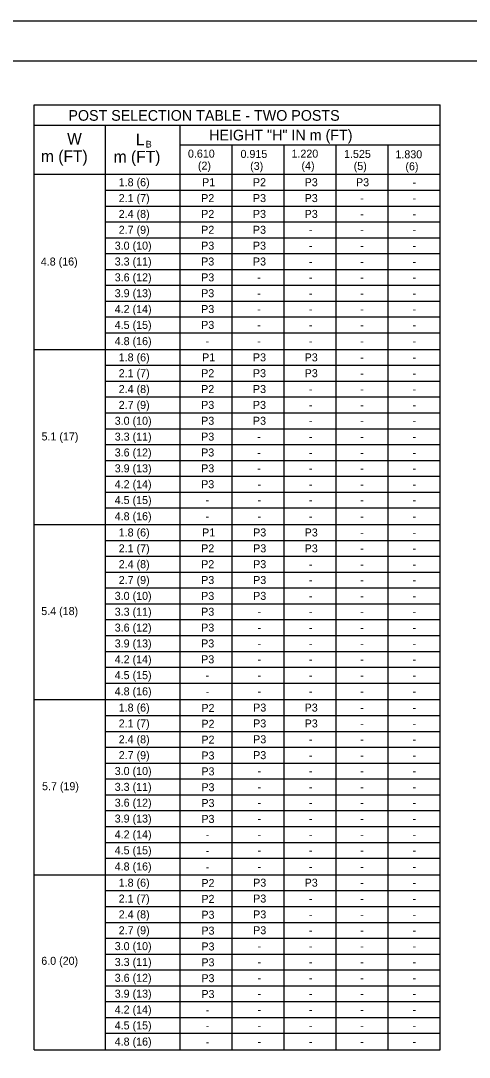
# Model space of a CAD drawing. Extents: x -1958 to 628, y -879 to 309.
# Drawn here: x -747.7 to -579.5, y -78.9 to 309.4 of the extents above; entities that cross this region are included whole.
import ezdxf

# ---------------------------------------------------------------- set-up
doc = ezdxf.new("R2010")
doc.units = 0
for name, color, linetype in [('1', 7, 'Continuous'), ('2', 7, 'Continuous'), ('PLT-BNDY', 7, 'Continuous')]:
    doc.layers.add(name, color=color, linetype=linetype)

msp = doc.modelspace()

# ---------------------------------------------------------------- linework, layer by layer
at = {"layer": '1'}
for p, q in [((-1077.39, 294.44), (-291.39, 294.44)), ((-742.69, 251.9), (-742.69, 277.92)), ((-742.69, 277.92), (-590.35, 277.92)), ((-590.35, 251.9), (-590.35, 277.92)), ((-742.69, 270.25), (-590.35, 270.25)), ((-715.89, -76.15), (-715.89, 270.25)), ((-687.88, -76.15), (-687.88, 270.25)), ((-668.38, -76.15), (-668.38, 262.9)), ((-648.87, -76.15), (-648.87, 262.9)), ((-629.36, -76.15), (-629.36, 262.9)), ((-609.85, -76.15), (-609.85, 262.9)), ((-742.69, -76.15), (-742.69, 251.9)), ((-742.69, 251.9), (-590.35, 251.9)), ((-649.54, 251.9), (-613.9, 251.9)), ((-613.9, 251.9), (-590.35, 251.9)), ((-590.35, -76.15), (-590.35, 251.9)), ((-715.89, 245.96), (-590.35, 245.96)), ((-715.89, 240.02), (-590.35, 240.02)), ((-649.54, 240.02), (-613.9, 240.02)), ((-613.9, 240.02), (-590.35, 240.02)), ((-715.89, 234.08), (-590.35, 234.08)), ((-715.89, 228.14), (-590.35, 228.14)), ((-715.89, 222.2), (-590.35, 222.2)), ((-715.89, 216.26), (-590.35, 216.26)), ((-715.89, 210.32), (-590.35, 210.32)), ((-715.89, 204.38), (-590.35, 204.38)), ((-715.89, 198.44), (-590.35, 198.44)), ((-715.89, 192.5), (-590.35, 192.5)), ((-742.69, 186.29), (-590.35, 186.29)), ((-715.89, 180.35), (-590.35, 180.35)), ((-715.89, 174.41), (-590.35, 174.41)), ((-715.89, 168.47), (-590.35, 168.47)), ((-715.89, 162.53), (-590.35, 162.53)), ((-715.89, 156.59), (-590.35, 156.59)), ((-715.89, 150.65), (-590.35, 150.65)), ((-715.89, 144.71), (-590.35, 144.71)), ((-715.89, 138.77), (-590.35, 138.77)), ((-715.89, 132.83), (-590.35, 132.83)), ((-715.89, 126.89), (-590.35, 126.89)), ((-742.69, 120.68), (-590.35, 120.68)), ((-715.89, 114.74), (-590.35, 114.74)), ((-715.89, 108.8), (-590.35, 108.8)), ((-715.89, 102.86), (-590.35, 102.86)), ((-715.89, 96.92), (-590.35, 96.92)), ((-715.89, 90.98), (-590.35, 90.98)), ((-715.89, 85.04), (-590.35, 85.04)), ((-715.89, 79.1), (-590.35, 79.1)), ((-715.89, 73.16), (-590.35, 73.16)), ((-715.89, 67.22), (-590.35, 67.22)), ((-715.89, 61.28), (-590.35, 61.28)), ((-742.69, 55.07), (-590.35, 55.07)), ((-715.89, 49.13), (-590.35, 49.13)), ((-715.89, 43.19), (-590.35, 43.19)), ((-715.89, 37.25), (-590.35, 37.25)), ((-715.89, 31.31), (-590.35, 31.31)), ((-715.89, 25.37), (-590.35, 25.37)), ((-715.89, 19.43), (-590.35, 19.43)), ((-715.89, 13.49), (-590.35, 13.49)), ((-715.89, 7.55), (-590.35, 7.55)), ((-715.89, 1.61), (-590.35, 1.61)), ((-715.89, -4.33), (-590.35, -4.33)), ((-742.69, -10.54), (-590.35, -10.54)), ((-613.9, -10.54), (-590.35, -10.54)), ((-715.89, -16.48), (-590.35, -16.48)), ((-613.9, -16.48), (-590.35, -16.48)), ((-715.89, -22.42), (-590.35, -22.42)), ((-613.9, -22.42), (-590.35, -22.42)), ((-715.89, -28.36), (-590.35, -28.36)), ((-613.9, -28.36), (-590.35, -28.36)), ((-715.89, -34.3), (-590.35, -34.3)), ((-715.89, -40.24), (-590.35, -40.24)), ((-613.9, -40.24), (-590.35, -40.24)), ((-715.89, -46.18), (-590.35, -46.18)), ((-613.9, -46.18), (-590.35, -46.18)), ((-715.89, -52.12), (-590.35, -52.12)), ((-613.9, -52.12), (-590.35, -52.12)), ((-715.89, -58.06), (-590.35, -58.06)), ((-613.9, -58.06), (-590.35, -58.06)), ((-715.89, -64), (-590.35, -64)), ((-613.9, -64), (-590.35, -64)), ((-715.89, -69.94), (-590.35, -69.94)), ((-613.9, -69.94), (-590.35, -69.94)), ((-742.69, -76.15), (-590.35, -76.15))]:
    msp.add_line(p, q, dxfattribs=at)
at = {"layer": '2'}
msp.add_line((-687.88, 262.9), (-590.35, 262.9), dxfattribs=at)
at = {"layer": 'PLT-BNDY'}
msp.add_lwpolyline([(-1117.39, 309.44), (-276.39, 309.44), (-276.39, -284.56), (-1117.39, -284.56)], close=True, dxfattribs=at)

# ---------------------------------------------------------------- texts
at = {"layer": '1'}
for s, height, p in [('POST SELECTION TABLE - TWO POSTS', 4.003, (-729.8, 271.96)), ('HEIGHT "H" IN m (FT)', 4.003, (-677.02, 264.6)), ('W', 4.37, (-730.29, 263.05)), ('L', 4.3, (-704.5, 262.77)), ('B', 2.5, (-700.8, 261.94)), ('m (FT)', 4.375, (-740.11, 256.48)), ('m (FT)', 4.375, (-712.84, 256.31)), ('0.610', 3, (-684.98, 258.14)), ('0.915', 3, (-665.26, 258.03)), ('1.220', 3, (-646.15, 258.14)), ('1.525', 3, (-626.43, 258.03)), ('1.830', 3, (-607.17, 257.9)), ('(2)', 3, (-681.24, 253.64)), ('(3)', 3, (-661.65, 253.53)), ('(4)', 3, (-642.4, 253.64)), ('(5)', 3, (-622.81, 253.53)), ('(6)', 3, (-603.42, 253.4)), ('1.8 (6)', 3, (-710.94, 247.43)), ('P1', 3, (-679.68, 247.43)), ('P2', 3, (-660.6, 247.43)), ('P3', 3, (-641.21, 247.43)), ('P3', 3, (-621.95, 247.43)), ('-', 3, (-600.73, 247.43)), ('2.1 (7)', 3, (-710.94, 241.49)), ('P2', 3, (-680.02, 241.49)), ('P3', 3, (-660.6, 241.49)), ('P3', 3, (-641.21, 241.49)), ('-', 3, (-620.33, 241.49)), ('-', 3, (-600.73, 241.49)), ('2.4 (8)', 3, (-710.94, 235.55)), ('P2', 3, (-680.02, 235.55)), ('P3', 3, (-660.6, 235.55)), ('P3', 3, (-641.21, 235.55)), ('-', 3, (-620.33, 235.55)), ('-', 3, (-600.73, 235.55)), ('2.7 (9)', 3, (-710.94, 229.61)), ('P2', 3, (-680.02, 229.61)), ('P3', 3, (-660.6, 229.61)), ('-', 3, (-639.59, 229.61)), ('-', 3, (-620.33, 229.61)), ('-', 3, (-600.73, 229.61)), ('3.0 (10)', 3, (-712.44, 223.67)), ('P3', 3, (-680.02, 223.67)), ('P3', 3, (-660.6, 223.67)), ('-', 3, (-639.59, 223.67)), ('-', 3, (-620.33, 223.67)), ('-', 3, (-600.73, 223.67)), ('4.8 (16)', 3, (-740.16, 217.71)), ('3.3 (11)', 3, (-712.44, 217.73)), ('P3', 3, (-680.02, 217.73)), ('P3', 3, (-660.6, 217.73)), ('-', 3, (-639.59, 217.73)), ('-', 3, (-620.33, 217.73)), ('-', 3, (-600.73, 217.73)), ('3.6 (12)', 3, (-712.44, 211.79)), ('P3', 3, (-680.02, 211.79)), ('-', 3, (-658.98, 211.79)), ('-', 3, (-639.59, 211.79)), ('-', 3, (-620.33, 211.79)), ('-', 3, (-600.73, 211.79)), ('3.9 (13)', 3, (-712.44, 205.85)), ('P3', 3, (-680.02, 205.85)), ('-', 3, (-658.98, 205.85)), ('-', 3, (-639.59, 205.85)), ('-', 3, (-620.33, 205.85)), ('-', 3, (-600.73, 205.85)), ('4.2 (14)', 3, (-712.44, 199.91)), ('P3', 3, (-680.02, 199.91)), ('-', 3, (-658.98, 199.91)), ('-', 3, (-639.59, 199.91)), ('-', 3, (-620.33, 199.91)), ('-', 3, (-600.73, 199.91)), ('4.5 (15)', 3, (-712.44, 193.97)), ('P3', 3, (-680.02, 193.97)), ('-', 3, (-658.98, 193.97)), ('-', 3, (-639.59, 193.97)), ('-', 3, (-620.33, 193.97)), ('-', 3, (-600.73, 193.97)), ('4.8 (16)', 3, (-712.44, 187.9)), ('-', 3, (-678.4, 187.9)), ('-', 3, (-658.98, 187.9)), ('-', 3, (-639.59, 187.9)), ('-', 3, (-620.33, 187.9)), ('-', 3, (-600.73, 187.9)), ('1.8 (6)', 3, (-710.94, 181.82)), ('P1', 3, (-679.68, 181.82)), ('P3', 3, (-660.6, 181.82)), ('P3', 3, (-641.21, 181.82)), ('-', 3, (-620.33, 181.82)), ('-', 3, (-600.73, 181.82)), ('2.1 (7)', 3, (-710.94, 175.88)), ('P2', 3, (-680.02, 175.88)), ('P3', 3, (-660.6, 175.88)), ('P3', 3, (-641.21, 175.88)), ('-', 3, (-620.33, 175.88)), ('-', 3, (-600.73, 175.88)), ('2.4 (8)', 3, (-710.94, 169.94)), ('P2', 3, (-680.02, 169.94)), ('P3', 3, (-660.6, 169.94)), ('-', 3, (-639.59, 169.94)), ('-', 3, (-620.33, 169.94)), ('-', 3, (-600.73, 169.94)), ('2.7 (9)', 3, (-710.94, 164)), ('P3', 3, (-680.02, 164)), ('P3', 3, (-660.6, 164)), ('-', 3, (-639.59, 164)), ('-', 3, (-620.33, 164)), ('-', 3, (-600.73, 164)), ('3.0 (10)', 3, (-712.44, 158.06)), ('P3', 3, (-680.02, 158.06)), ('P3', 3, (-660.6, 158.06)), ('-', 3, (-639.59, 158.06)), ('-', 3, (-620.33, 158.06)), ('-', 3, (-600.73, 158.06)), ('5.1 (17)', 3, (-739.88, 152.19)), ('3.3 (11)', 3, (-712.44, 152.12)), ('P3', 3, (-680.02, 152.12)), ('-', 3, (-658.98, 152.12)), ('-', 3, (-639.59, 152.12)), ('-', 3, (-620.33, 152.12)), ('-', 3, (-600.73, 152.12)), ('3.6 (12)', 3, (-712.44, 146.18)), ('P3', 3, (-680.02, 146.18)), ('-', 3, (-658.98, 146.18)), ('-', 3, (-639.59, 146.18)), ('-', 3, (-620.33, 146.18)), ('-', 3, (-600.73, 146.18)), ('3.9 (13)', 3, (-712.44, 140.24)), ('P3', 3, (-680.02, 140.24)), ('-', 3, (-658.95, 140.24)), ('-', 3, (-639.59, 140.24)), ('-', 3, (-620.33, 140.24)), ('-', 3, (-600.73, 140.24)), ('4.2 (14)', 3, (-712.44, 134.3)), ('P3', 3, (-680.02, 134.3)), ('-', 3, (-658.9, 134.3)), ('-', 3, (-639.59, 134.3)), ('-', 3, (-620.33, 134.3)), ('-', 3, (-600.73, 134.3)), ('4.5 (15)', 3, (-712.44, 128.36)), ('-', 3, (-678.4, 128.36)), ('-', 3, (-658.9, 128.36)), ('-', 3, (-639.59, 128.36)), ('-', 3, (-620.33, 128.36)), ('-', 3, (-600.73, 128.36)), ('4.8 (16)', 3, (-712.44, 122.29)), ('-', 3, (-678.4, 122.29)), ('-', 3, (-658.9, 122.29)), ('-', 3, (-639.59, 122.29)), ('-', 3, (-620.33, 122.29)), ('-', 3, (-600.73, 122.29)), ('1.8 (6)', 3, (-710.94, 116.21)), ('P1', 3, (-679.68, 116.21)), ('P3', 3, (-660.52, 116.21)), ('P3', 3, (-641.21, 116.21)), ('-', 3, (-620.33, 116.21)), ('-', 3, (-600.73, 116.21)), ('2.1 (7)', 3, (-710.94, 110.27)), ('P2', 3, (-680.02, 110.27)), ('P3', 3, (-660.52, 110.27)), ('P3', 3, (-641.21, 110.27)), ('-', 3, (-620.33, 110.27)), ('-', 3, (-600.73, 110.27)), ('2.4 (8)', 3, (-710.94, 104.33)), ('P2', 3, (-680.02, 104.33)), ('P3', 3, (-660.52, 104.33)), ('-', 3, (-639.59, 104.33)), ('-', 3, (-620.33, 104.33)), ('-', 3, (-600.73, 104.33)), ('2.7 (9)', 3, (-710.94, 98.39)), ('P3', 3, (-680.02, 98.39)), ('P3', 3, (-660.52, 98.39)), ('-', 3, (-639.59, 98.39)), ('-', 3, (-620.33, 98.39)), ('-', 3, (-600.73, 98.39)), ('3.0 (10)', 3, (-712.44, 92.45)), ('P3', 3, (-680.02, 92.45)), ('P3', 3, (-660.52, 92.45)), ('-', 3, (-639.59, 92.45)), ('-', 3, (-620.33, 92.45)), ('-', 3, (-600.73, 92.45)), ('5.4 (18)', 3, (-739.98, 86.76)), ('3.3 (11)', 3, (-712.44, 86.51)), ('P3', 3, (-680.02, 86.51)), ('-', 3, (-658.9, 86.51)), ('-', 3, (-639.59, 86.51)), ('-', 3, (-620.33, 86.51)), ('-', 3, (-600.73, 86.51)), ('3.6 (12)', 3, (-712.44, 80.57)), ('P3', 3, (-680.02, 80.57)), ('-', 3, (-658.9, 80.57)), ('-', 3, (-639.59, 80.57)), ('-', 3, (-620.33, 80.57)), ('-', 3, (-600.73, 80.57)), ('3.9 (13)', 3, (-712.44, 74.63)), ('P3', 3, (-680.02, 74.63)), ('-', 3, (-658.9, 74.63)), ('-', 3, (-639.59, 74.63)), ('-', 3, (-620.33, 74.63)), ('-', 3, (-600.73, 74.63)), ('4.2 (14)', 3, (-712.44, 68.69)), ('P3', 3, (-680.02, 68.69)), ('-', 3, (-658.9, 68.69)), ('-', 3, (-639.59, 68.69)), ('-', 3, (-620.33, 68.69)), ('-', 3, (-600.73, 68.69)), ('4.5 (15)', 3, (-712.44, 62.75)), ('-', 3, (-678.4, 62.75)), ('-', 3, (-658.9, 62.75)), ('-', 3, (-639.59, 62.75)), ('-', 3, (-620.33, 62.75)), ('-', 3, (-600.73, 62.75)), ('4.8 (16)', 3, (-712.44, 56.68)), ('-', 3, (-678.31, 56.54)), ('-', 3, (-658.9, 56.68)), ('-', 3, (-639.59, 56.68)), ('-', 3, (-620.33, 56.68)), ('-', 3, (-600.73, 56.68)), ('1.8 (6)', 3, (-710.94, 50.6)), ('P2', 3, (-679.93, 50.47)), ('P3', 3, (-660.52, 50.6)), ('P3', 3, (-641.21, 50.6)), ('-', 3, (-620.33, 50.6)), ('-', 3, (-600.73, 50.6)), ('2.1 (7)', 3, (-710.94, 44.66)), ('P2', 3, (-679.93, 44.53)), ('P3', 3, (-660.52, 44.66)), ('P3', 3, (-641.21, 44.66)), ('-', 3, (-620.33, 44.66)), ('-', 3, (-600.73, 44.66)), ('2.4 (8)', 3, (-710.94, 38.72)), ('P2', 3, (-679.93, 38.59)), ('P3', 3, (-660.52, 38.72)), ('-', 3, (-639.59, 38.72)), ('-', 3, (-620.33, 38.72)), ('-', 3, (-600.73, 38.72)), ('2.7 (9)', 3, (-710.94, 32.78)), ('P3', 3, (-679.93, 32.65)), ('P3', 3, (-660.52, 32.78)), ('-', 3, (-639.59, 32.78)), ('-', 3, (-620.33, 32.78)), ('-', 3, (-600.73, 32.78)), ('3.0 (10)', 3, (-712.44, 26.84)), ('P3', 3, (-679.93, 26.71)), ('-', 3, (-658.9, 26.84)), ('-', 3, (-639.59, 26.84)), ('-', 3, (-620.33, 26.84)), ('-', 3, (-600.73, 26.84)), ('5.7 (19)', 3, (-739.69, 21.15)), ('3.3 (11)', 3, (-712.44, 20.9)), ('P3', 3, (-679.93, 20.77)), ('-', 3, (-658.9, 20.9)), ('-', 3, (-639.59, 20.9)), ('-', 3, (-620.33, 20.9)), ('-', 3, (-600.73, 20.9)), ('3.6 (12)', 3, (-712.44, 14.96)), ('P3', 3, (-679.93, 14.83)), ('-', 3, (-658.9, 14.96)), ('-', 3, (-639.59, 14.96)), ('-', 3, (-620.33, 14.96)), ('-', 3, (-600.73, 14.96)), ('3.9 (13)', 3, (-712.44, 9.02)), ('P3', 3, (-679.93, 8.89)), ('-', 3, (-658.9, 9.02)), ('-', 3, (-639.59, 9.02)), ('-', 3, (-620.33, 9.02)), ('-', 3, (-600.73, 9.02)), ('4.2 (14)', 3, (-712.44, 3.08)), ('-', 3, (-678.31, 2.95)), ('-', 3, (-658.9, 3.08)), ('-', 3, (-639.59, 3.08)), ('-', 3, (-620.33, 3.08)), ('-', 3, (-600.73, 3.08)), ('4.5 (15)', 3, (-712.44, -2.86)), ('-', 3, (-678.31, -2.99)), ('-', 3, (-658.9, -2.86)), ('-', 3, (-639.59, -2.86)), ('-', 3, (-620.33, -2.86)), ('-', 3, (-600.73, -2.86)), ('4.8 (16)', 3, (-712.44, -8.93)), ('-', 3, (-678.31, -9.07)), ('-', 3, (-658.9, -8.93)), ('-', 3, (-639.59, -8.93)), ('-', 3, (-620.33, -8.93)), ('-', 3, (-600.73, -8.93)), ('1.8 (6)', 3, (-710.94, -15.01)), ('P2', 3, (-679.93, -15.14)), ('P3', 3, (-660.52, -15.01)), ('P3', 3, (-641.21, -15.01)), ('-', 3, (-620.33, -15.01)), ('-', 3, (-600.73, -15.01)), ('2.1 (7)', 3, (-710.94, -20.95)), ('P2', 3, (-679.93, -21.08)), ('P3', 3, (-660.52, -20.95)), ('-', 3, (-639.59, -20.95)), ('-', 3, (-620.33, -20.95)), ('-', 3, (-600.73, -20.95)), ('2.4 (8)', 3, (-710.94, -26.89)), ('P3', 3, (-679.93, -27.02)), ('P3', 3, (-660.52, -26.89)), ('-', 3, (-639.59, -26.89)), ('-', 3, (-620.33, -26.89)), ('-', 3, (-600.73, -26.89)), ('2.7 (9)', 3, (-710.94, -32.83)), ('P3', 3, (-679.93, -32.96)), ('P3', 3, (-660.52, -32.83)), ('-', 3, (-639.59, -32.83)), ('-', 3, (-620.33, -32.83)), ('-', 3, (-600.73, -32.83)), ('3.0 (10)', 3, (-712.44, -38.77)), ('P3', 3, (-679.93, -38.9)), ('-', 3, (-658.9, -38.77)), ('-', 3, (-639.59, -38.77)), ('-', 3, (-620.33, -38.77)), ('-', 3, (-600.73, -38.77)), ('6.0 (20)', 3, (-739.98, -44.28)), ('3.3 (11)', 3, (-712.44, -44.71)), ('P3', 3, (-679.93, -44.84)), ('-', 3, (-658.9, -44.71)), ('-', 3, (-639.59, -44.71)), ('-', 3, (-620.33, -44.71)), ('-', 3, (-600.73, -44.71)), ('3.6 (12)', 3, (-712.44, -50.65)), ('P3', 3, (-679.93, -50.78)), ('-', 3, (-658.9, -50.65)), ('-', 3, (-639.59, -50.65)), ('-', 3, (-620.33, -50.65)), ('-', 3, (-600.73, -50.65)), ('3.9 (13)', 3, (-712.44, -56.59)), ('P3', 3, (-679.93, -56.72)), ('-', 3, (-658.9, -56.59)), ('-', 3, (-639.59, -56.59)), ('-', 3, (-620.33, -56.59)), ('-', 3, (-600.73, -56.59)), ('4.2 (14)', 3, (-712.44, -62.53)), ('-', 3, (-678.31, -62.66)), ('-', 3, (-658.9, -62.53)), ('-', 3, (-639.59, -62.53)), ('-', 3, (-620.33, -62.53)), ('-', 3, (-600.73, -62.53)), ('4.5 (15)', 3, (-712.44, -68.47)), ('-', 3, (-678.31, -68.6)), ('-', 3, (-658.9, -68.47)), ('-', 3, (-639.59, -68.47)), ('-', 3, (-620.33, -68.47)), ('-', 3, (-600.73, -68.47)), ('4.8 (16)', 3, (-712.44, -74.54)), ('-', 3, (-678.31, -74.68)), ('-', 3, (-658.9, -74.54)), ('-', 3, (-639.59, -74.54)), ('-', 3, (-620.33, -74.54)), ('-', 3, (-600.73, -74.54))]:
    msp.add_text(s, height=height, dxfattribs=at).set_placement(p)

doc.saveas('drawing.dxf')
